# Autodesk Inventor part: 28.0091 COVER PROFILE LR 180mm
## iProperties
Created: 2007-06
Part Number: 28.0091 COVER PROFILE LR 180mm
Material: Aluminum-6061
Document SubType Name: Modeling
Designer: Andy Moles
Mass: 65.4559 g
Surface Area: 334.596 cm^2
Volume: 24.1535 cm^3
Density: 2.71 g/cm^3
Author: Andy Moles
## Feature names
1. Extrusion1
